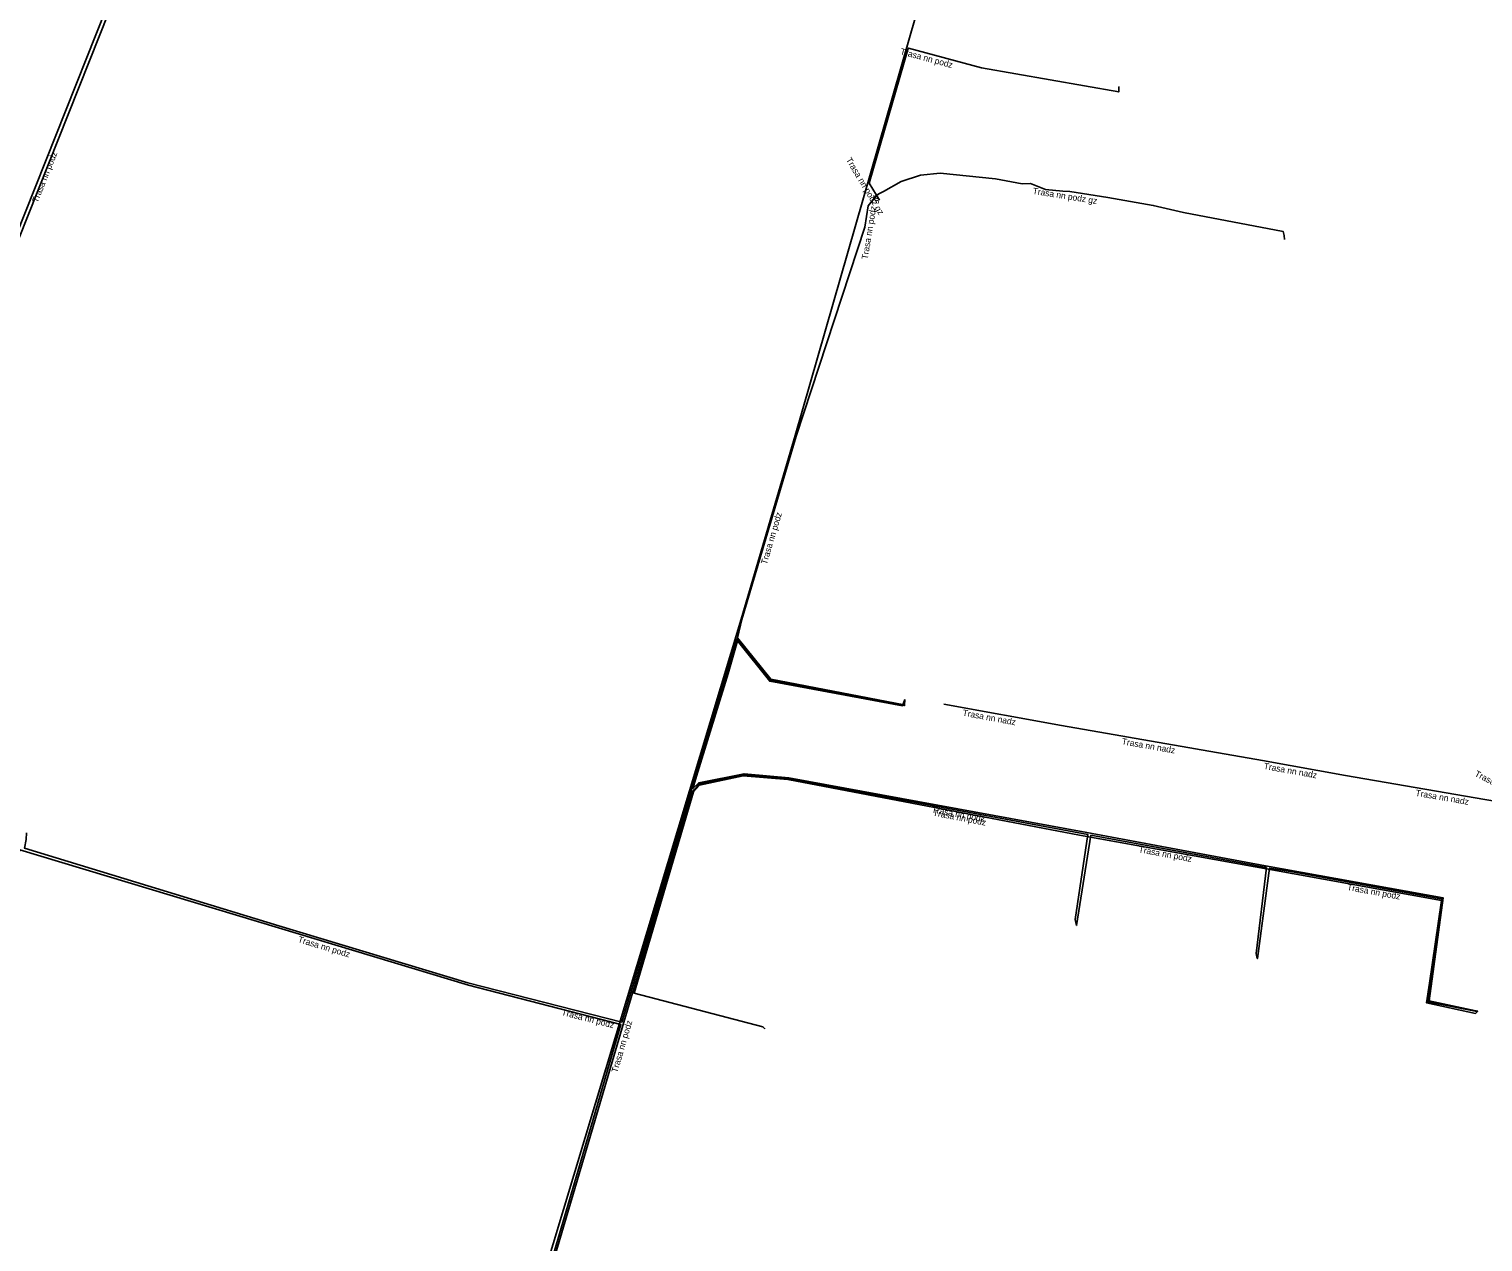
# Model space of a CAD drawing. Extents: x -875087 to -874407, y -1056142 to -1055396.
# Drawn here: x -874634 to -874518.7, y -1055714.8 to -1055618.7 of the extents above; entities that cross this region are included whole.
import ezdxf

# ---------------------------------------------------------------- set-up
doc = ezdxf.new("R2010")
doc.units = 0
for name, color, linetype in [('Popiskový text - Ostatní atributy Trasy', 7, 'Continuous'), ('Spojnice NN', 7, 'Continuous'), ('Spojnice VN', 7, 'Continuous')]:
    doc.layers.add(name, color=color, linetype=linetype)

msp = doc.modelspace()

# ---------------------------------------------------------------- linework, layer by layer
at = {"layer": 'Spojnice NN'}
for points in [[(-874612.48, -1055559.82), (-874612.35, -1055560.11), (-874609.64, -1055561.04), (-874615.01, -1055584.78), (-874653.49, -1055681.61), (-874664.04, -1055676.9), (-874670.32, -1055675.68), (-874671.63, -1055675.74)], [(-874566.8, -1055631.89), (-874567.37, -1055630.93), (-874566.5, -1055627.93), (-874564.3, -1055620.35), (-874564.26, -1055620.23), (-874558.48, -1055621.79), (-874547.59, -1055623.71), (-874547.59, -1055623.33), (-874547.54, -1055623.34)], [(-874566.8, -1055631.89), (-874566.45, -1055631.7), (-874566.24, -1055631.59), (-874564.83, -1055630.8), (-874563.3, -1055630.32), (-874561.74, -1055630.14), (-874557.36, -1055630.6), (-874555.26, -1055630.99), (-874554.59, -1055630.96), (-874553.41, -1055631.44), (-874552.03, -1055631.57), (-874551.48, -1055631.6), (-874548.45, -1055632.08), (-874544.86, -1055632.71), (-874542.47, -1055633.26), (-874534.57, -1055634.77), (-874534.48, -1055635.1), (-874534.46, -1055635.4)], [(-874567.73, -1055634.44), (-874567.45, -1055632.73), (-874567.06, -1055632.23), (-874566.8, -1055631.89)], [(-874566.8, -1055631.89), (-874566.56, -1055632.29)], [(-874564.56, -1055671.87), (-874564.6, -1055672.27), (-874575.16, -1055670.26), (-874577.82, -1055666.97), (-874577.46, -1055665.53), (-874573.15, -1055650.99), (-874567.73, -1055634.44)], [(-874634.17, -1055682.43), (-874634.19, -1055682.95), (-874634.32, -1055683.65), (-874614.15, -1055689.79), (-874599.17, -1055694.31), (-874586.99, -1055697.42), (-874581.03, -1055677.56), (-874578.66, -1055669.75), (-874577.85, -1055667.03), (-874575.19, -1055670.33), (-874564.57, -1055672.34), (-874564.56, -1055671.87)], [(-874519.14, -1055696.57), (-874519.28, -1055696.53), (-874523, -1055695.75), (-874521.87, -1055687.58), (-874535.97, -1055685.05), (-874550.12, -1055682.41), (-874573.73, -1055678.07), (-874577.29, -1055677.75), (-874580.88, -1055678.46), (-874581.35, -1055678.92), (-874580.95, -1055677.6), (-874578.54, -1055669.81), (-874577.82, -1055667.21), (-874575.25, -1055670.41), (-874564.73, -1055672.36), (-874564.56, -1055671.87)], [(-874561.46, -1055672.22), (-874552.12, -1055673.93)], [(-874552.12, -1055673.93), (-874536.21, -1055676.69)], [(-874671.63, -1055675.74), (-874672.14, -1055676.1), (-874672.09, -1055676.23), (-874668.05, -1055686.51), (-874655.68, -1055691.44), (-874653.63, -1055685.73), (-874636.77, -1055691.66), (-874636.4, -1055690.52), (-874634.68, -1055683.78), (-874614.19, -1055689.95), (-874599.12, -1055694.49), (-874587.05, -1055697.61), (-874589.41, -1055705.68), (-874592.97, -1055717.79), (-874593.11, -1055718.28), (-874600.61, -1055742.94), (-874589.46, -1055747.15), (-874589.08, -1055746.44), (-874588.99, -1055746.23)], [(-874536.21, -1055676.69), (-874529.63, -1055677.87)], [(-874550.95, -1055689.78), (-874550.94, -1055689.78), (-874551.04, -1055689.29), (-874550.04, -1055682.57), (-874573.74, -1055678.15), (-874577.33, -1055677.82), (-874579.36, -1055678.23), (-874580.83, -1055678.55), (-874581.37, -1055679.12), (-874586.83, -1055697.42), (-874589.24, -1055705.69), (-874592.83, -1055717.84), (-874593.02, -1055718.41), (-874600.46, -1055742.88), (-874589.38, -1055747.07), (-874589.06, -1055746.46), (-874588.99, -1055746.23)], [(-874575.64, -1055697.97), (-874575.64, -1055697.97), (-874575.8, -1055697.81), (-874586, -1055695.12), (-874581.29, -1055679.18), (-874580.82, -1055678.65), (-874577.35, -1055677.9), (-874573.83, -1055678.21), (-874550.7, -1055682.62), (-874533.86, -1055685.66), (-874522.02, -1055687.79), (-874522.97, -1055694.35), (-874523.2, -1055695.91), (-874519.31, -1055696.74), (-874519.14, -1055696.57)], [(-874529.63, -1055677.87), (-874512.14, -1055680.9)], [(-874536.61, -1055692.39), (-874536.61, -1055692.39), (-874536.71, -1055691.98), (-874535.89, -1055685.18), (-874549.8, -1055682.62), (-874550.94, -1055689.78), (-874550.95, -1055689.78)], [(-874519.14, -1055696.57), (-874519.21, -1055696.58), (-874523.1, -1055695.82), (-874522.88, -1055694.37), (-874521.93, -1055687.67), (-874533.83, -1055685.52), (-874535.65, -1055685.23), (-874536.6, -1055692.39), (-874536.61, -1055692.39)]]:
    msp.add_lwpolyline(points, dxfattribs=at)
at = {"layer": 'Spojnice VN'}
for points in [[(-874671.62, -1055675.74), (-874664.18, -1055677.12), (-874653.33, -1055682.01), (-874614.75, -1055584.92), (-874608.13, -1055555.88), (-874592.2, -1055524.96), (-874588.97, -1055504.43), (-874585.67, -1055482.27), (-874580.15, -1055462.49), (-874586.24, -1055458.27), (-874612, -1055448.91), (-874634.66, -1055436.86), (-874633.37, -1055428.2), (-874633.11, -1055424.46), (-874629.83, -1055396.03)], [(-874406.69, -1055581.15), (-874406.71, -1055581.26), (-874408.66, -1055584.81), (-874410.36, -1055595.17), (-874541.67, -1055569.99), (-874544.6, -1055569.23), (-874545.33, -1055569.04), (-874546.42, -1055568.86), (-874547.03, -1055569.04), (-874547.54, -1055569.23), (-874547.94, -1055569.41), (-874548.44, -1055570.02), (-874549.06, -1055571.07), (-874549.53, -1055571.87), (-874549.86, -1055572.74), (-874550.13, -1055574.32), (-874562.47, -1055613.42), (-874573.23, -1055650.94), (-874577.52, -1055665.5)], [(-874577.52, -1055665.5), (-874603.15, -1055750.63), (-874659.41, -1055728.79), (-874653.48, -1055710.73), (-874660.19, -1055679.23), (-874664.25, -1055677.37), (-874671.5, -1055675.74)]]:
    msp.add_lwpolyline(points, dxfattribs=at)

# ---------------------------------------------------------------- texts
at = {"layer": 'Popiskový text - Ostatní atributy Trasy'}
for s, rotation, p in [('Trasa nn podz', 344.9699, (-874564.95, -1055620.72)), ('Trasa nn podz', 68.3256, (-874633.28, -1055632.53)), ('Trasa nn podz gz', 300.9638, (-874569.24, -1055629.09)), ('Trasa nn podz gz', 350.9982, (-874554.44, -1055631.79)), ('Trasa nn podz gz', 80.7008, (-874567.49, -1055637.01)), ('Trasa nn podz', 73.4982, (-874575.49, -1055661.2)), ('Trasa nn nadz', 349.6254, (-874560, -1055673.14)), ('Trasa nn nadz', 350.1546, (-874547.38, -1055675.41)), ('Trasa nn nadz', 349.7987, (-874536.13, -1055677.36)), ('Trasa nn nadz izol', 332.9514, (-874519.43, -1055677.9)), ('Trasa nn nadz', 350.188, (-874524.1, -1055679.49)), ('Trasa nn podz', 349.5676, (-874562.45, -1055680.81)), ('Trasa nn podz', 349.1902, (-874562.35, -1055681.06)), ('Trasa nn podz', 349.5817, (-874546.05, -1055683.97)), ('Trasa nn podz', 349.7593, (-874529.52, -1055686.96)), ('Trasa nn podz', 343.2378, (-874612.69, -1055691.08)), ('Trasa nn podz', 345.6841, (-874591.79, -1055696.86)), ('Trasa nn podz', 73.7761, (-874587.33, -1055701.47))]:
    msp.add_text(s, height=0.5, rotation=rotation, dxfattribs=at).set_placement(p)

doc.saveas('drawing.dxf')
